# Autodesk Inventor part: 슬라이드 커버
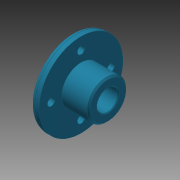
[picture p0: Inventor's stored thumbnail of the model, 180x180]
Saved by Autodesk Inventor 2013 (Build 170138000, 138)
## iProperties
Created: 2015-12
Part Number: 슬라이드 커버
Document SubType Name: Modeling
Designer: mdu
Density: 2.71 g/cm^3
Material: 알루미늄 6061
Mass: 53.5737 g
Surface Area: 81.0277 cm^2
Volume: 19.7689 cm^3
Author: mdu
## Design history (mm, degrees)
sketch "스케치1"
  geometry: L1 (-12, 0)-(12, 0); L2 (-12, 0)-(-12, 28); L3 (-12, 28)-(-6, 28); L4 (-6, 28)-(-6, 13); L5 (-6, 13)-(12, 13); L6 (12, 13)-(12, 0); 2 further points
  constraints: 12 end point, 3 perpendicular, 1 coincident, 1 horizontal, 1 midpoint, 1 parallel
  dimensions: "d1" = 56 diameter of L3 L1; "d2" = 26 diameter of L5 L1; "d5" = 6 distance of L2.end L3.end; "d32" = 18 distance of L4.end L5.end
revolve "회전1" sketch "스케치1" stored, may be unused: angle "d6" = 90 deg
sketch "스케치2" dims "d33" = 40
  geometry: 3 further points
  constraints: 2 vertical alignment, 1 coincident, 2 other
hole "구멍1" sketch "스케치2" at (0, 20) diameter "d8" = 5; stored, may be unused: countersink angle "d12" = 90 deg, drill point angle "d14" = 118 deg; dims "d9" = 6, "d10" = 8, "d11" = 4.4, "d13" = 8
hole "구멍2" diameter "d20" = 14; stored, may be unused: countersink angle "d24" = 90 deg, drill point angle "d26" = 0 deg; dims "d18" = 10, "d19" = 10, "d21" = 6, "d22" = 8, "d23" = 4.4, "d25" = 8
fillet "모깎기1" dims "d27" = 3
chamfer "모따기1" distance "d29" = 1; stored, may be unused: second distance "d30" = 2, angle "d31" = 45 deg
chamfer "모따기2" distance "d35" = 0.5; stored, may be unused: second distance "d36" = 2, angle "d37" = 45 deg
node "솔리드1"
pattern_circular "원형 패턴1" dims angle "d16" = 360 deg
